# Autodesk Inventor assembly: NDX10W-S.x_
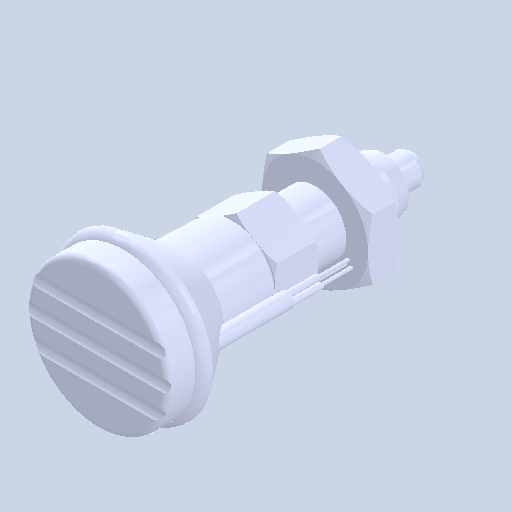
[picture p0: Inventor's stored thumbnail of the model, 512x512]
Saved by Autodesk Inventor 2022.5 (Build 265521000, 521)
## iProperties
Created: 2024-05
Part Number: NDX10W-S.x_
Document SubType Name: Assembly
Designer: ImaoCorp
Author: ImaoCorp
Sending System: SOLIDWORKS 2022-2022290
MC: AMD64
MC_MODEL: Intel64 Family 6 Model 60 Stepping 3, GenuineIntel
OS: Windows_NT
FRU: Parasolid Version 33.1, build 260,  4-25-2022
FORMAT: text
GUISE: transmit
KEY: FILENDX10W-S.x_t
DATE: Tue May 21 08:48:03 2024
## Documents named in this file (3)
- X:\14_SW2022-Inv2022\保留中\kipp\KME_データ\n\ndx10w-s\NDX10W-S.x_.iam
- X:\14_SW2022-Inv2022\保留中\kipp\KME_データ\n\ndx10w-s\NDX10W-S_01.ipt
- X:\14_SW2022-Inv2022\保留中\kipp\KME_データ\n\ndx10w-s\NDX10W-S_02.ipt
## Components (2 placed, 2 different names)
1. NDX10W-S_01
2. NDX10W-S_02
